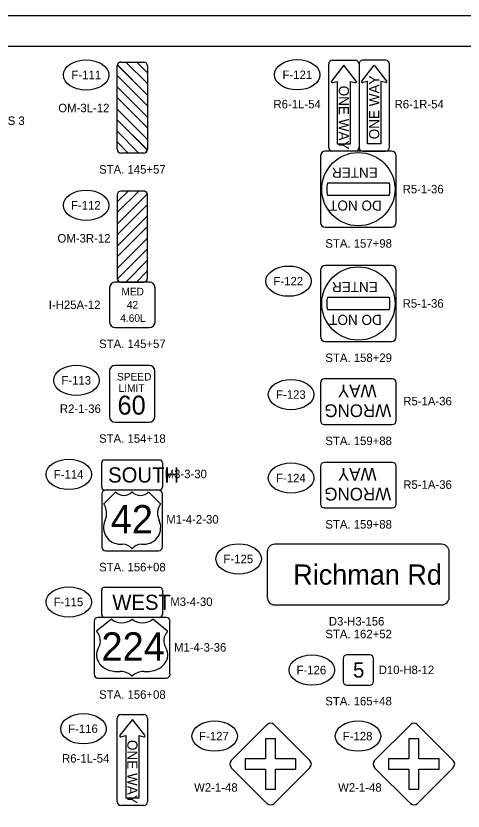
# Model space of a CAD drawing. Extents: x 0 to 34, y 0 to 22.
# Drawn here: x 19.05 to 26.42, y 8.89 to 22 of the extents above; entities that cross this region are included whole.
import ezdxf

# ---------------------------------------------------------------- set-up
doc = ezdxf.new("R2010")
doc.units = 0
for name, color, linetype in [('SH_Border', 7, 'Continuous'), ('SH_Cut_Line', 7, 'Continuous'), ('SH_Text', 7, 'Continuous'), ('SN_P_Signs', 7, 'Continuous')]:
    doc.layers.add(name, color=color, linetype=linetype)

msp = doc.modelspace()

# ---------------------------------------------------------------- linework, layer by layer
at = {"layer": 'SH_Border'}
msp.add_lwpolyline([(1.5, 21.5), (33.5, 21.5), (33.5, 0.5), (1.5, 0.5)], close=True, dxfattribs=at)
at = {"layer": 'SH_Cut_Line'}
msp.add_lwpolyline([(0, 0), (34, 0), (34, 22), (0, 22)], close=True, dxfattribs=at)
at = {"layer": 'SH_Text'}
for centre in [(20.208, 21.026), (23.689, 21.029), (20.208, 18.877), (23.546, 17.626), (20.048, 15.991), (23.588, 15.756), (19.922, 14.44), (23.588, 14.38), (22.723, 13.046), (19.922, 12.336), (23.931, 11.214), (20.164, 10.245), (22.328, 10.124), (24.692, 10.124)]:
    msp.add_ellipse(centre, major_axis=(0.375, 0), ratio=0.666667, dxfattribs=at)
at = {"layer": 'SN_P_Signs'}
for p, q in [((21.221, 20.695), (20.721, 21.195)), ((21.221, 20.884), (20.865, 21.239)), ((21.221, 21.06), (21.042, 21.239)), ((24.458, 21.185), (24.253, 20.925)), ((24.664, 20.925), (24.458, 21.185)), ((24.753, 20.925), (24.959, 21.185)), ((24.959, 21.185), (25.164, 20.925)), ((21.221, 20.518), (20.721, 21.018)), ((24.27, 20.9), (24.349, 20.921)), ((24.349, 20.921), (24.349, 19.893)), ((24.568, 19.893), (24.568, 20.921)), ((24.568, 20.921), (24.648, 20.9)), ((24.849, 20.921), (24.769, 20.9)), ((24.849, 19.893), (24.849, 20.921)), ((25.148, 20.9), (25.068, 20.921)), ((25.068, 20.921), (25.068, 19.893)), ((21.221, 20.33), (20.721, 20.83)), ((21.221, 20.153), (20.721, 20.653)), ((21.221, 19.964), (20.721, 20.464)), ((21.221, 19.787), (20.721, 20.287)), ((21.08, 19.739), (20.721, 20.099)), ((20.904, 19.739), (20.721, 19.922)), ((24.349, 19.893), (24.568, 19.893)), ((25.068, 19.893), (24.849, 19.893)), ((24.187, 19.247), (25.208, 19.247)), ((20.721, 18.756), (21.076, 19.111)), ((20.721, 18.933), (20.899, 19.111)), ((20.721, 18.567), (21.221, 19.067)), ((25.208, 19.039), (24.187, 19.039)), ((20.721, 18.391), (21.221, 18.891)), ((20.721, 18.202), (21.221, 18.702)), ((20.721, 18.025), (21.221, 18.525)), ((20.721, 17.836), (21.221, 18.336)), ((20.721, 17.66), (21.221, 18.16)), ((20.861, 17.611), (21.221, 17.971)), ((21.038, 17.611), (21.221, 17.794)), ((24.187, 17.362), (25.208, 17.362)), ((25.208, 17.154), (24.187, 17.154)), ((20.466, 14.231), (20.466, 14.631)), ((20.516, 14.681), (21.416, 14.681)), ((21.466, 14.631), (21.466, 14.231)), ((21.416, 14.181), (20.516, 14.181)), ((20.693, 14.149), (20.498, 13.954)), ((21.435, 13.954), (21.24, 14.149)), ((20.771, 13.29), (20.81, 13.29)), ((21.123, 13.29), (21.162, 13.29)), ((20.466, 12.131), (20.466, 12.531)), ((20.516, 12.581), (21.416, 12.581)), ((21.466, 12.531), (21.466, 12.131)), ((21.416, 12.081), (20.516, 12.081)), ((20.625, 12.05), (20.381, 11.855)), ((21.552, 11.855), (21.308, 12.05)), ((20.722, 11.191), (20.771, 11.191)), ((21.162, 11.191), (21.211, 11.191)), ((20.971, 10.397), (20.766, 10.138)), ((21.177, 10.138), (20.971, 10.397)), ((20.782, 10.113), (20.862, 10.133)), ((20.862, 10.133), (20.862, 9.105)), ((21.081, 9.105), (21.081, 10.133)), ((21.081, 10.133), (21.161, 10.113)), ((23.333, 10.08), (23.166, 10.08)), ((23.166, 10.08), (23.166, 9.747)), ((23.333, 9.747), (23.333, 10.08)), ((25.697, 10.08), (25.531, 10.08)), ((25.531, 10.08), (25.531, 9.747)), ((25.697, 9.747), (25.697, 10.08)), ((23.166, 9.747), (22.833, 9.747)), ((22.833, 9.747), (22.833, 9.58)), ((23.666, 9.747), (23.333, 9.747)), ((23.666, 9.58), (23.666, 9.747)), ((25.531, 9.747), (25.197, 9.747)), ((25.197, 9.747), (25.197, 9.58)), ((26.031, 9.747), (25.697, 9.747)), ((26.031, 9.58), (26.031, 9.747)), ((22.833, 9.58), (23.166, 9.58)), ((23.166, 9.58), (23.166, 9.247)), ((23.333, 9.247), (23.333, 9.58)), ((23.333, 9.58), (23.666, 9.58)), ((25.197, 9.58), (25.531, 9.58)), ((25.531, 9.58), (25.531, 9.247)), ((25.697, 9.247), (25.697, 9.58)), ((25.697, 9.58), (26.031, 9.58)), ((23.166, 9.247), (23.333, 9.247)), ((25.531, 9.247), (25.697, 9.247)), ((20.862, 9.105), (21.081, 9.105))]:
    msp.add_line(p, q, dxfattribs=at)
for points in [[(24.271, 21.268), (24.646, 21.268)], [(25.146, 21.268), (24.771, 21.268)], [(20.721, 19.801), (20.721, 21.176)], [(20.783, 21.239), (20.865, 21.239), (21.221, 20.884), (21.221, 20.695), (20.723, 21.193)], [(20.783, 21.239), (21.158, 21.239)], [(21.042, 21.239), (21.158, 21.239)], [(21.221, 21.176), (21.221, 21.06), (21.042, 21.239)], [(21.221, 21.176), (21.221, 19.801)], [(24.209, 19.831), (24.209, 21.206)], [(24.709, 21.206), (24.709, 19.831)], [(24.709, 21.206), (24.709, 19.831)], [(25.209, 19.831), (25.209, 21.206)], [(20.721, 20.83), (20.721, 21.018), (21.221, 20.518), (21.221, 20.33), (20.721, 20.83)], [(20.721, 20.464), (20.721, 20.653), (21.221, 20.153), (21.221, 19.964), (20.721, 20.464)], [(21.158, 19.739), (21.08, 19.739), (20.721, 20.099), (20.721, 20.287), (21.219, 19.789)], [(20.721, 19.801), (20.721, 19.922), (20.904, 19.739)], [(21.158, 19.739), (20.783, 19.739)], [(20.904, 19.739), (20.783, 19.739)], [(24.073, 19.69), (24.073, 18.596)], [(25.244, 19.768), (24.151, 19.768)], [(24.646, 19.768), (24.271, 19.768)], [(24.771, 19.768), (25.146, 19.768)], [(25.323, 18.596), (25.323, 19.69)], [(20.721, 19.049), (20.721, 18.933), (20.899, 19.111)], [(21.158, 19.111), (21.076, 19.111), (20.721, 18.756), (20.721, 18.567), (21.218, 19.065)], [(20.721, 19.049), (20.721, 17.674)], [(21.158, 19.111), (20.783, 19.111)], [(20.899, 19.111), (20.783, 19.111)], [(21.221, 17.674), (21.221, 19.049)], [(21.221, 18.702), (21.221, 18.891), (20.721, 18.391), (20.721, 18.202), (21.221, 18.702)], [(21.221, 18.336), (21.221, 18.525), (20.721, 18.025), (20.721, 17.836), (21.221, 18.336)], [(24.151, 18.518), (25.244, 18.518)], [(20.783, 17.611), (20.861, 17.611), (21.221, 17.971), (21.221, 18.16), (20.722, 17.661)], [(25.244, 17.883), (24.151, 17.883)], [(21.221, 17.674), (21.221, 17.794), (21.038, 17.611)], [(24.073, 17.805), (24.073, 16.711)], [(25.323, 16.711), (25.323, 17.805)], [(21.252, 17.611), (20.689, 17.611)], [(20.783, 17.611), (21.158, 17.611)], [(21.038, 17.611), (21.158, 17.611)], [(20.596, 17.517), (20.596, 16.955)], [(21.346, 16.955), (21.346, 17.517)], [(20.689, 16.861), (21.252, 16.861)], [(24.151, 16.633), (25.244, 16.633)], [(20.591, 16.144), (20.591, 15.394)], [(21.248, 16.238), (20.685, 16.238)], [(21.341, 15.394), (21.341, 16.144)], [(25.26, 16.013), (24.135, 16.013)], [(24.073, 15.951), (24.073, 15.326)], [(25.323, 15.326), (25.323, 15.951)], [(20.685, 15.301), (21.248, 15.301)], [(24.135, 15.263), (25.26, 15.263)], [(24.073, 14.574), (24.073, 13.949)], [(25.26, 14.637), (24.135, 14.637)], [(25.323, 13.949), (25.323, 14.574)], [(21.404, 14.181), (20.529, 14.181)], [(20.466, 14.118), (20.466, 13.243)], [(21.466, 13.243), (21.466, 14.118)], [(24.135, 13.887), (25.26, 13.887)], [(26.07, 13.288), (23.32, 13.288)], [(20.529, 13.181), (21.404, 13.181)], [(23.195, 13.163), (23.195, 12.413)], [(26.195, 12.413), (26.195, 13.163)], [(23.32, 12.288), (26.07, 12.288)], [(21.529, 12.081), (20.404, 12.081)], [(20.341, 12.019), (20.341, 11.144)], [(21.591, 11.144), (21.591, 12.019)], [(24.884, 11.464), (24.509, 11.464)], [(24.446, 11.402), (24.446, 11.027)], [(24.946, 11.027), (24.946, 11.402)], [(20.404, 11.081), (21.529, 11.081)], [(24.509, 10.964), (24.884, 10.964)], [(20.721, 9.043), (20.721, 10.418)], [(20.784, 10.48), (21.159, 10.48)], [(21.221, 10.418), (21.221, 9.043)], [(23.191, 10.312), (22.602, 9.722)], [(23.898, 9.722), (23.309, 10.312)], [(25.555, 10.312), (24.966, 9.722)], [(26.262, 9.722), (25.673, 10.312)], [(22.602, 9.604), (23.191, 9.015)], [(23.309, 9.015), (23.898, 9.604)], [(24.966, 9.604), (25.555, 9.015)], [(25.673, 9.015), (26.262, 9.604)], [(21.159, 8.98), (20.784, 8.98)]]:
    msp.add_lwpolyline(points, dxfattribs=at)
for centre in [(24.698, 19.143), (24.698, 17.258)]:
    msp.add_circle(centre, 0.604, dxfattribs=at)
for centre, radius, start, end in [((24.271, 21.206), 0.0625, 90, 180), ((24.646, 21.206), 0.0625, 360, 90), ((24.771, 21.206), 0.0625, 90, 180), ((25.146, 21.206), 0.0625, 360, 90), ((20.783, 21.176), 0.0625, 90, 180), ((20.783, 21.176), 0.0625, 90, 164.7237), ((21.158, 21.176), 0.0625, 0, 90), ((21.158, 21.176), 0.0625, 0, 90), ((24.266, 20.915), 0.0157, 141.6275, 284.2432), ((24.652, 20.915), 0.0157, 255.7826, 38.342), ((24.765, 20.915), 0.0157, 141.658, 284.2174), ((25.152, 20.915), 0.0157, 255.7568, 38.3725), ((20.783, 19.801), 0.0625, 180, 270), ((20.783, 19.801), 0.0625, 180, 270), ((21.158, 19.801), 0.0625, 270, 360), ((24.271, 19.831), 0.0625, 180, 270), ((24.646, 19.831), 0.0625, 270, 360), ((24.771, 19.831), 0.0625, 180, 270), ((25.146, 19.831), 0.0625, 270, 360), ((21.158, 19.801), 0.0625, 270, 348.268), ((24.151, 19.69), 0.0781, 90, 180), ((25.244, 19.69), 0.0781, 0, 90), ((24.698, 19.143), 0.521, 168.463, 191.537), ((24.698, 19.143), 0.521, 348.463, 11.537), ((20.783, 19.049), 0.0625, 90, 180), ((20.783, 19.049), 0.0625, 90, 180), ((21.158, 19.049), 0.0625, 0, 90), ((21.158, 19.049), 0.0625, 15.2763, 90), ((24.151, 18.596), 0.0781, 180, 270), ((25.244, 18.596), 0.0781, 270, 360), ((24.151, 17.805), 0.0781, 90, 180), ((25.244, 17.805), 0.0781, 0, 90), ((20.689, 17.517), 0.0938, 90, 180), ((20.783, 17.674), 0.0625, 180, 270), ((20.783, 17.674), 0.0625, 191.732, 270), ((21.158, 17.674), 0.0625, 270, 0), ((21.158, 17.674), 0.0625, 270, 0), ((21.252, 17.517), 0.0938, 0, 90), ((24.698, 17.258), 0.521, 168.463, 191.537), ((24.698, 17.258), 0.521, 348.463, 11.537), ((20.689, 16.955), 0.0938, 180, 270), ((21.252, 16.955), 0.0938, 270, 0), ((24.151, 16.711), 0.0781, 180, 270), ((25.244, 16.711), 0.0781, 270, 360), ((20.685, 16.144), 0.0938, 90, 180), ((21.248, 16.144), 0.0938, 0, 90), ((24.135, 15.951), 0.0625, 90, 180), ((25.26, 15.951), 0.0625, 0, 90), ((20.685, 15.394), 0.0938, 180, 270), ((21.248, 15.394), 0.0938, 270, 0), ((24.135, 15.326), 0.0625, 180, 270), ((25.26, 15.326), 0.0625, 270, 360), ((20.516, 14.631), 0.05, 90, 180), ((21.416, 14.631), 0.05, 0, 90), ((24.135, 14.574), 0.0625, 90, 180), ((25.26, 14.574), 0.0625, 0, 90), ((20.516, 14.231), 0.05, 180, 270), ((20.529, 14.118), 0.0625, 90, 180), ((21.404, 14.118), 0.0625, 0, 90), ((21.416, 14.231), 0.05, 270, 0), ((20.83, 14.289), 0.195, 225.573, 314.427), ((21.103, 14.289), 0.195, 225.573, 314.427), ((20.274, 13.797), 0.273, 334.5471, 35.0009), ((21.659, 13.797), 0.273, 144.9991, 205.4529), ((24.135, 13.949), 0.0625, 180, 270), ((25.26, 13.949), 0.0625, 270, 360), ((20.768, 13.563), 0.273, 154.8319, 270.6383), ((21.165, 13.563), 0.273, 269.3617, 25.1681), ((20.529, 13.243), 0.0625, 180, 270), ((20.81, 13.095), 0.195, 36.8699, 90), ((21.123, 13.095), 0.195, 90, 143.1301), ((21.404, 13.243), 0.0625, 270, 0), ((23.32, 13.163), 0.125, 90, 180), ((26.07, 13.163), 0.125, 0, 90), ((20.516, 12.531), 0.05, 90, 180), ((21.416, 12.531), 0.05, 0, 90), ((23.32, 12.413), 0.125, 180, 270), ((26.07, 12.413), 0.125, 270, 0), ((20.404, 12.019), 0.0625, 90, 180), ((20.516, 12.131), 0.05, 180, 270), ((21.416, 12.131), 0.05, 270, 0), ((21.529, 12.019), 0.0625, 0, 90), ((24.509, 11.402), 0.0625, 90, 180), ((24.884, 11.402), 0.0625, 0, 90), ((20.404, 11.144), 0.0625, 180, 270), ((21.529, 11.144), 0.0625, 270, 0), ((24.509, 11.027), 0.0625, 180, 270), ((24.884, 11.027), 0.0625, 270, 0), ((20.784, 10.418), 0.0625, 90, 180), ((21.159, 10.418), 0.0625, 360, 90), ((23.25, 10.253), 0.0833, 45, 135), ((25.614, 10.253), 0.0833, 45, 135), ((20.778, 10.128), 0.0157, 141.6275, 284.2432), ((21.164, 10.128), 0.0157, 255.7826, 38.342), ((22.66, 9.663), 0.0833, 135, 225), ((23.839, 9.663), 0.0833, 315, 45), ((25.025, 9.663), 0.0833, 135, 225), ((26.203, 9.663), 0.0833, 315, 45), ((20.784, 9.043), 0.0625, 180, 270), ((21.159, 9.043), 0.0625, 270, 360), ((23.25, 9.074), 0.0833, 225, 315), ((25.614, 9.074), 0.0833, 225, 315)]:
    msp.add_arc(centre, radius, start, end, dxfattribs=at)
for centre, major_axis, start_param, end_param in [((20.796, 12.19), (-0.244, 0), 0.795399, 2.346194), ((21.137, 12.19), (-0.244, 0), 0.795399, 2.346194), ((20.101, 11.698), (0.342, 0), 5.838949, 6.894067), ((21.832, 11.698), (-0.342, 0), 5.672304, 6.727422), ((20.719, 11.464), (0.342, 0), 2.702327, 4.723529), ((21.214, 11.464), (-0.342, 0), 1.559657, 3.580859), ((20.771, 10.995), (-0.244, 0), 3.785094, 4.712389), ((21.162, 10.995), (-0.244, 0), 4.712389, 5.639684)]:
    msp.add_ellipse(centre, major_axis=major_axis, ratio=0.8, start_param=start_param, end_param=end_param, dxfattribs=at)

# ---------------------------------------------------------------- texts
at = {"layer": 'SH_Text'}
for s, p in [('F-111', (19.966, 20.956)), ('F-121', (23.447, 20.959)), ('R6-1L-54', (23.298, 20.475)), ('R6-1R-54', (25.295, 20.475)), ('OM-3L-12', (19.749, 20.412)), ('THE CONTRACTOR SHALL REFER TO SHEETS 3', (14.847, 20.202)), ('STA. 145+57', (20.422, 19.399)), ('R5-1-36', (25.428, 19.074)), ('F-112', (19.959, 18.807)), ('OM-3R-12', (19.736, 18.263)), ('STA. 157+98', (24.153, 18.178)), ('F-122', (23.297, 17.556)), ('I-H25A-12', (19.592, 17.166)), ('R5-1-36', (25.428, 17.189)), ('STA. 145+57', (20.422, 16.523)), ('STA. 158+29', (24.154, 16.293)), ('F-113', (19.8, 15.921)), ('F-123', (23.34, 15.686)), ('R5-1A-36', (25.438, 15.578)), ('R2-1-36', (19.775, 15.453)), ('STA. 154+18', (20.422, 14.961)), ('STA. 159+88', (24.153, 14.923)), ('F-114', (19.674, 14.37)), ('M3-3-30', (21.503, 14.377)), ('F-124', (23.34, 14.31)), ('R5-1A-36', (25.438, 14.202)), ('M1-4-2-30', (21.53, 13.629)), ('STA. 159+88', (24.153, 13.547)), ('F-125', (22.473, 12.976)), ('STA. 156+08', (20.422, 12.841)), ('F-115', (19.672, 12.266)), ('M3-4-30', (21.596, 12.27)), ('D3-H3-156', (24.211, 11.948)), ('STA. 162+52', (24.153, 11.738)), ('M1-4-3-36', (21.657, 11.518)), ('F-126', (23.678, 11.144)), ('D10-H8-12', (25.033, 11.147)), ('STA. 156+08', (20.422, 10.74)), ('STA. 165+48', (24.152, 10.631)), ('F-116', (19.912, 10.175)), ('F-127', (22.072, 10.054)), ('F-128', (24.441, 10.054)), ('R6-1L-54', (19.811, 9.687)), ('W2-1-48', (21.989, 9.208)), ('W2-1-48', (24.364, 9.208))]:
    msp.add_text(s, height=0.14, dxfattribs=at).set_placement(p)
at = {"layer": 'SN_P_Signs'}
for s, height, rotation, p in [('ONE WAY', 0.1667, 90, (25.042, 19.965)), ('ONE WAY', 0.1667, 270, (24.375, 20.849)), ('ENTER', 0.1667, 180, (25.017, 19.497)), ('DO NOT', 0.1667, 180, (25.083, 18.956)), ('ENTER', 0.1667, 180, (25.017, 17.612)), ('DO NOT', 0.1667, 180, (25.083, 17.071)), ('WAY', 0.2094, 180, (24.998, 15.92)), ('WRONG', 0.2094, 180, (25.24, 15.595)), ('WAY', 0.2094, 180, (24.998, 14.544)), ('WRONG', 0.2094, 180, (25.24, 14.219)), ('ONE WAY', 0.1667, 270, (20.888, 10.061))]:
    msp.add_text(s, height=height, rotation=rotation, dxfattribs=at).set_placement(p)
for s, height, p in [('MED', 0.125, (20.79, 17.392)), ('42', 0.125, (20.88, 17.174)), ('4.60L', 0.125, (20.771, 16.955)), ('SPEED', 0.125, (20.718, 15.988)), ('LIMIT', 0.125, (20.744, 15.801)), ('60', 0.3125, (20.726, 15.426)), ('SOUTH', 0.25, (20.571, 14.306)), ('42', 0.4688, (20.613, 13.466)), ('Richman Rd', 0.3333, (23.623, 12.621)), ('WEST', 0.25, (20.64, 12.206)), ('224', 0.4688, (20.461, 11.367)), ('5', 0.25, (24.61, 11.089))]:
    msp.add_text(s, height=height, dxfattribs=at).set_placement(p)

doc.saveas('drawing.dxf')
